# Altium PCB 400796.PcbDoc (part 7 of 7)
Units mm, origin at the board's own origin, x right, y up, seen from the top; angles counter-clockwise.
Board outline 53 x 53 mm, 6 copper layers (Top Layer, Mid Layer 1, Mid Layer 2, Mid Layer 3, Mid Layer 4, Bottom Layer), stack 1.494 mm thick; 319 components, 236 nets, 1249 pads, 2569 vias.
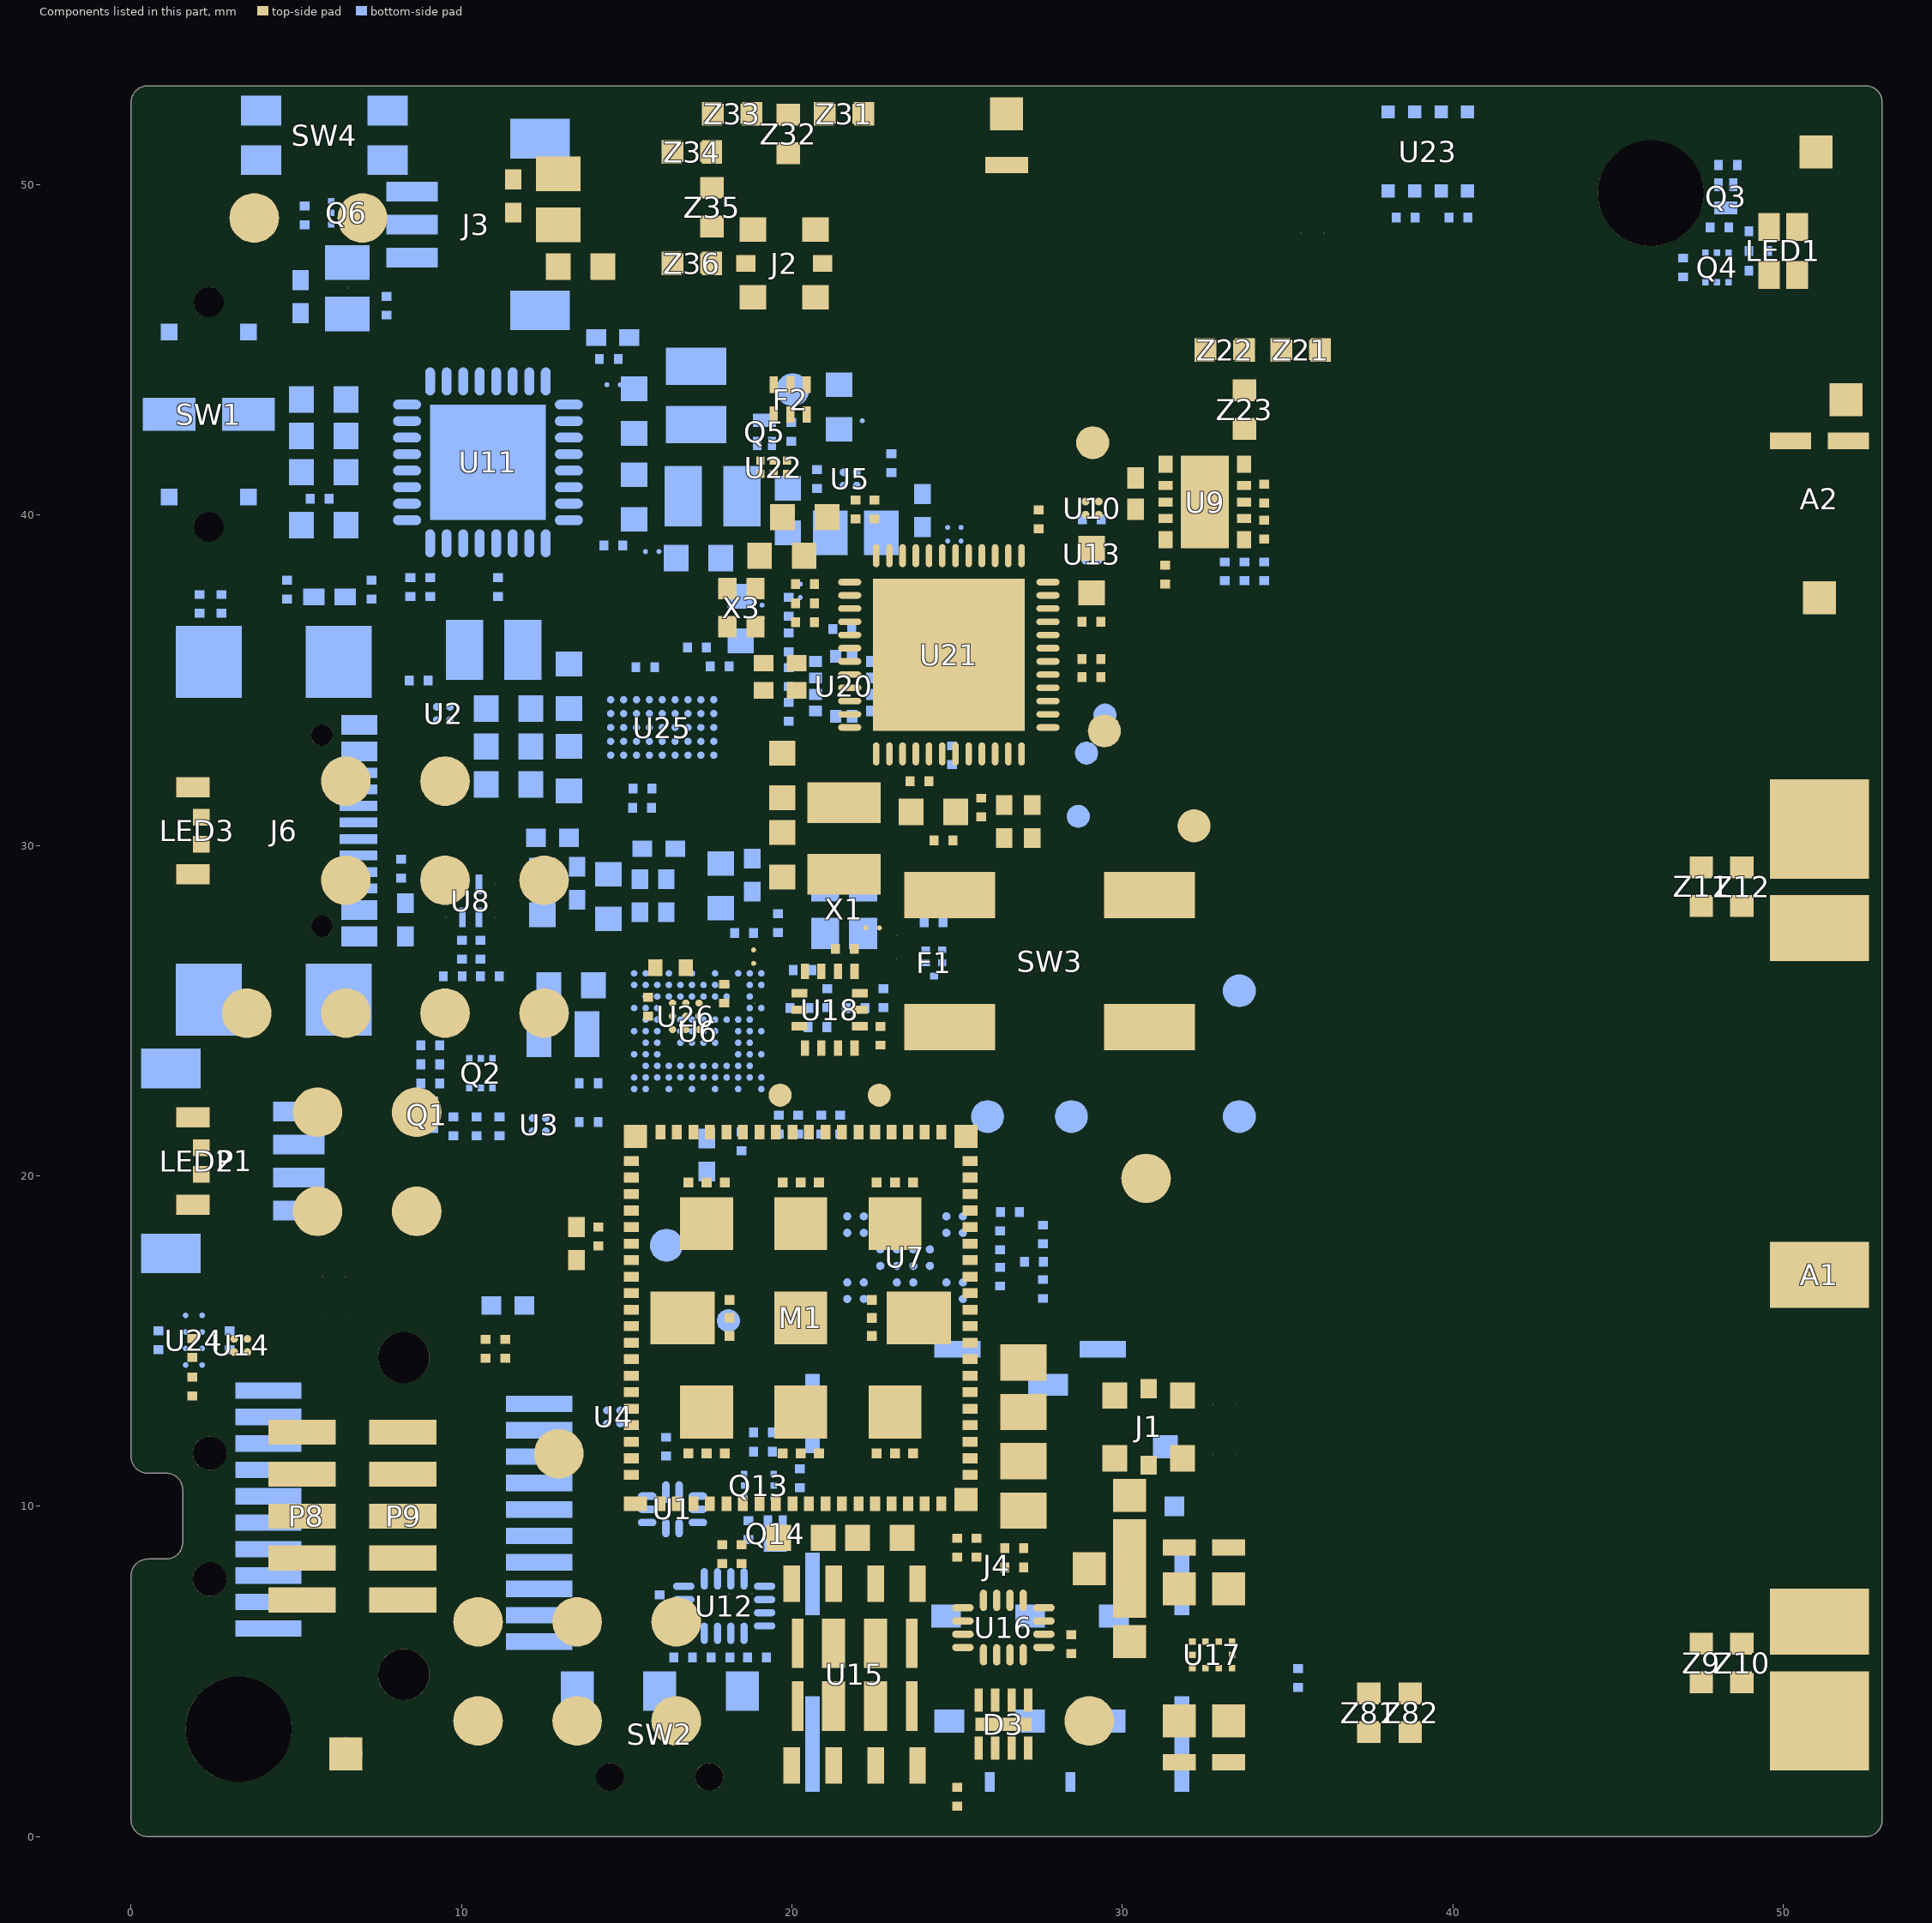
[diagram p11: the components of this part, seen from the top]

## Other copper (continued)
Bottom Layer:
  rectangle net 1V8_SW: 17.495,37.175 19.614,37.925
  region net 3V3_IND: 18.487,38.314 18.487,39.989 17.987,39.989 17.987,38.314
  region net 3V3: 9.275,13.075 9.275,11.4 9.775,11.4 9.775,13.075
  region net VBAT_nRF70: 9.375,33.25 8.4,33.25 8.4,31.45 9.375,31.45
  rectangle net VOUT_BUCK3: 9.525,31.45 10.655,33.4
  region net VBUS: 6.925,37.9 6.925,38.4 5.075,38.4 5.075,37.9
  rectangle net VBUS_CONN: 7.225,32.55 7.75,33.15
  region net GND: 23.794,26.876 23.794,28.176 23.33,28.176 23.33,26.876
  region net VSYS_SW: 10.65,16.725 10.65,15.05 11.15,15.05 11.15,16.725
  rectangle net GND: 22.25,25.836 23.2,26.125
  rectangle net GND: 16.525,23.88 17.775,24.88
  region net SW3: 14.168,33.155 14.245,33.232 cw(c14.3,33.178) 14.3,33.255 14.487,33.255 14.487,33.095 14.263,32.87 14.168,32.965 14.168,33.154
  region net VSYS_SW: 14.33,32.43 cw(c14.48,32.43) 14.374,32.536 14.458,32.62 14.458,32.664 14.479,32.664 14.499,32.644 14.496,32.641 14.496,32.438
  region net SW0: 14.168,33.995 14.245,33.918 ccw(c14.3,33.972) 14.3,33.895 14.487,33.895 14.487,34.055 14.263,34.28 14.168,34.185 14.168,33.996
  region net VSYS_SW: 14.33,34.72 ccw(c14.48,34.72) 14.374,34.614 14.458,34.53 14.458,34.486 14.479,34.486 14.499,34.506 14.496,34.509 14.496,34.712
  region net VBAT_nRF70: 8.4,32.975 8.4,33.175 cw(c8.65,33.175) 8.65,33.425 ccw(c8.65,33.624) 8.791,33.483 9.001,33.694 9.001,32.975 8.7,32.975
  region net VOUT_BUCK3: 10.375,32.975 10.375,33.175 ccw(c10.125,33.175) 10.125,33.425 cw(c10.125,33.624) 9.984,33.483 9.774,33.694 9.774,32.975 10.075,32.975
  region net VOUT_BUCK3: 9.525,33.8 cw(c9.65,33.8) 9.65,33.925 cw(c9.65,33.804) 9.735,33.89 9.75,33.875 cw(c8.905,33.03) 10.1,33.03 10.1,32.8 9.575,32.8 cw(c9.695,32.921) 9.525,32.921 9.525,33.425
  region net VBAT_nRF70: 9.375,33.8 ccw(c9.25,33.8) 9.25,33.925 ccw(c9.25,33.804) 9.165,33.89 9.15,33.875 ccw(c9.995,33.03) 8.8,33.03 8.8,32.8 9.325,32.8 ccw(c9.205,32.921) 9.375,32.921 9.375,33.425
  region net VDD_nRF53: 12.275,21.35 ccw(c12.15,21.35) 12.15,21.475 ccw(c12.15,21.354) 12.065,21.44 12.05,21.425 ccw(c12.895,20.58) 11.7,20.58 11.7,20.175 12.2,20.175 12.2,20.29 cw(c12.285,20.29) 12.225,20.35 ccw(c12.104,20.471) 12.275,20.471 12.275,20.975
  region net 1V8_SW: 12.425,21.35 cw(c12.55,21.35) 12.55,21.475 cw(c12.55,21.354) 12.635,21.44 12.65,21.425 cw(c11.805,20.58) 13,20.58 13,20.175 12.5,20.175 12.5,20.29 ccw(c12.415,20.29) 12.475,20.35 cw(c12.596,20.471) 12.425,20.471 12.425,20.975
  region net VDD_nRF91_RES: 14.4,12.625 cw(c14.4,12.5) 14.525,12.5 cw(c14.404,12.5) 14.49,12.415 14.475,12.4 cw(c13.63,13.245) 13.63,12.05 13.225,12.05 13.225,12.55 13.34,12.55 ccw(c13.34,12.635) 13.4,12.575 cw(c13.521,12.454) 13.521,12.625 14.025,12.625
  region net VDD_nRF91: 14.4,12.775 ccw(c14.4,12.9) 14.525,12.9 ccw(c14.404,12.9) 14.49,12.985 14.475,13 ccw(c13.63,12.155) 13.63,13.35 13.225,13.35 13.225,12.85 13.34,12.85 cw(c13.34,12.765) 13.4,12.825 ccw(c13.521,12.946) 13.521,12.775 14.025,12.775
  region net 1V8_IND: 17.393,46.2 16.593,47 14.5,47 13.525,47 13.525,45.572 14.375,45.572 14.375,45.885 14.69,46.2
  region net VSYS: 3.047,45.05 3.047,46.622 5.099,46.622 7.222,46.622 7.222,45.572 5.067,45.572 4.545,45.05
  region net 3V3: 22.425,39.897 22.425,39.042 24.798,39.042 24.798,39.897 22.468,39.897
  region net VBUS: 7.499,42.178 7.677,42 8.577,42 8.663,41.914 8.663,41.765 8.599,41.7 7.491,41.7 7.313,41.878 5.829,41.878 5.829,42.803 6.874,42.803
  pour cut-out: 20.85,36 20.85,34.25 23.05,34.25 23.05,36 23.075,36
  region net VBUS: 5.85,37.775 5.975,37.9 6.225,37.9 6.225,38.4 4.832,38.4 4.575,38.143 4.575,37.9 5.075,37.9 5.2,37.775 5.2,37.675 5.85,37.675
  pour cut-out: 11.725,32.6 11.125,32.6 11.125,34.55 11.725,34.55
  region net VBUS_CONN: 8.623,28.523 9.7,28.523 9.7,29.255 8.405,29.255 7.5,28.35 7.325,28.35 7.325,27.75 7.85,27.75
  region net VBAT: 8.4,40.7 7.875,40.7 7,39.825 6.475,39.3 6.025,39.3 6.025,40.1 6.6,40.1 6.7,40.2 7.5,41 8.4,41
  pour cut-out: 12.65,43.45 8.95,43.45 8.95,39.75 12.65,39.75
  region net PVSS1: 15.625,45.65 14.875,45.65 14.875,44.949 14.309,44.383 13.8,44.383 13.8,43.225 13.575,43 13.25,43 13.25,42.7 13.775,42.7 14.525,43.45 15.625,43.45
  region net NetC9_2: 14.3,42 14.825,42.525 14.825,42.85 15.625,42.85 15.625,40.85 14.825,40.85 14.825,41.175 14.3,41.7
  region net 1V8_IND: 15.772,46.2 16.175,45.797 16.175,43.925 18.01,43.925 18.01,45.583 16.868,46.725 15.772,46.725
  pour cut-out: 18.264,43.925 18.264,41.485 16.175,41.485 16.175,43.925
  region net 3V3_IND: 19.068,38.889 21.362,38.889 21.569,39.096 21.569,39.938 21.428,40.079 19.149,40.079 19.05,40.178 19.05,41.485 17.9,41.485 17.9,39.65 17.475,39.225 17.475,38.3 18.479,38.3
  region net PVSS2: 13.25,41 13.8,41 14.55,40.25 15.625,40.25 15.625,39.875 16.4,39.1 17.275,39.1 17.275,38.3 15.1,38.3 14.75,38.65 14.75,39.525 13.575,40.7 13.25,40.7
  pour cut-out: 17.3,38.834 17.3,38.045 13.938,38.045 13.938,38.834
  pour cut-out: 3.425,42.05 3.425,41.19
  region net NetC9_2: 7.191,41.703 7.394,41.5 8.605,41.5 8.687,41.418 8.687,41.27 8.617,41.2 7.363,41.2 6.941,40.778 5.829,40.778 5.829,41.703
  pour cut-out: 36.75,48.311 42.25,48.311 42.25,53.229 36.75,53.229
  region net 1V8_SW: 12.5,20.175 12.5,19.6 12.675,19.425 13,19.425 13,20.2 12.5,20.2
  region net VDD_nRF53: 11.7,20.175 11.7,19.6 11.875,19.425 12.2,19.425 12.2,20.2 11.7,20.2
  pour cut-out: 19.85,26.38 19.85,29.505 23.266,29.505 23.266,26.38
  pour cut-out: 17.45,26.18 17.45,24.73 19.225,24.73 19.225,26.18
  pour cut-out: 20.87,26.08 20.87,25.925 21.35,25.925 21.35,25.355 19.175,25.355 19.175,26.08
Multi-Layer:
  pour cut-out: 38.628,45.61 38.628,44.39 33.098,44.39 33.098,45.61
  pour cut-out: 33.098,44.405 33.098,42.009 34.32,42.009 34.32,44.405
  pour cut-out: 16.97,51.555 16.97,47.048 18.191,47.048 18.191,51.555
  pour cut-out: 22.5,52.76 22.5,51.54 16.97,51.54 16.97,52.76
  pour cut-out: 22.5,53 30.5,53 30.5,45 22.5,45
  pour cut-out: 36.6,0.25 36.6,47 54.2,47 54.2,0.25

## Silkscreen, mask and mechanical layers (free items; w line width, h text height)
Top Overlay:
  region: 38.855,52.403 ccw(c38.602,49.887) 38.855,47.37 38.855,48.129 cw(c38.602,49.887) 38.855,51.644
  region: 41.167,50.266 cw(c42.902,49.887) 43.155,51.644 43.155,52.403 ccw(c42.902,49.887) 43.155,47.37 43.155,48.129 cw(c42.902,49.887) 41.167,49.507 42.902,49.507 42.902,50.266
  text "'.PCBNumber'" at 43.89,51.58 h1.78
  text "BUTTON 2" at 1.35,50.95 h1.8
  text "LED1" at 51.099,49.979 h1.8 r270
  text "ON" at 0.136,47.55 h1.8 r270
  text "POWER" at 2.85,47.55 h1.8 r270
  text ".PCBRevision" at 43.889,47.214 h1.02
  text "OFF" at 0.136,42.05 h1.8 r270
  text "For evaluation only; / not FCC approved for resale." at 4.054,40.687 h1.4
  text "Thingy:91 X" at 6.875,37.896 h1.78
  text "CHARGE LED" at 2.609,33.858 h1.8 r270
  text "LED2" at 2.681,22.168 h1.8 r270
  text "BUTTON 1" at 23.3,21.866 h1.8
  text "SWD" at 14.5,1.375 h1.4
  text "nRF53" at 12.35,0.15 h1.4
  text "nRF91" at 15.95,0.15 h1.4
Board Outline:
  lines w0.15: 52.5,0 ccw(c52.5,0.5) 53,0.5 ; 52.5,0 ccw(c52.5,0.5) 53,0.5 ; 52.5,0 0.5,0 cw(c0.5,0.5) 0,0.5 0,7.9 cw(c0.5,7.9) 0.5,8.4 1.06,8.4 ccw(c1.06,8.9) 1.56,8.9 1.56,10.5 ccw(c1.06,10.5) 1.06,11 0.5,11 cw(c0.5,11.5) 0,11.5 0,52.5 cw(c0.5,52.5) 0.5,53 52.5,53 cw(c52.5,52.5) 53,52.5 53,0.5
Board Other:
  drawing of 2516 lines, arcs and shapes, not listed
Dimension:
  drawing of 463 lines, arcs and shapes, not listed
Top Impedance Info:
  lines w0.29: 18.075,30.9 17.502,30.9 cw(c17.502,32.048) 16.354,32.048 16.354,40.077 cw(c17.526,40.077) 17.526,41.25 19.05,41.25 ; 19.45,41.682 19.45,43.15 ; 19.875,41.25 22.85,41.25 cw(c22.85,40.35) 23.75,40.35 23.75,38.775 ; 19.95,43.95 19.95,44.376 cw(c21.024,44.376) 20.265,45.136 20.275,45.146 cw(c20.8,44.622) 20.8,45.364 ccw(c20.8,45.959) 21.22,45.538 21.254,45.572 ccw(c20.421,46.406) 21.6,46.406 21.6,47.201 ccw(c21.173,47.201) 21.475,47.503 ccw(c21.183,47.211) 21.183,47.623 20.928,47.623 ; 20.475,43.05 23.324,43.05 cw(c23.324,41.824) 24.55,41.824 24.55,38.775
  lines w0.638: 24.513,22.086 24.513,22 cw(c25.436,22) 24.783,22.652 cw(c25.367,22.068) 25.367,22.894 32.036,22.894 ccw(c32.036,25.169) 33.645,23.56 ccw(c32.075,25.131) 34.296,25.131 34.296,31.648 ccw(c31.756,31.648) 33.552,33.444 32.039,34.956 cw(c33.836,36.752) 31.296,36.752 31.296,37.78 ; 26.06,17.946 27.386,17.946 cw(c27.386,15.406) 29.182,17.202 30.056,16.328 cw(c28.26,14.532) 30.8,14.532 30.8,13.557 ; 30.564,10.64 ccw(c29.994,11.21) 30.8,11.21 ; 31.312,38.625 31.312,39.256 ; 33.687,41.543 33.687,42.577 33.7,42.59 ; 33.7,43.81 33.7,44.99 33.71,45 34.79,45
  text "50 ohm impedance, CPW" at 11.45,29.05 h1.78
  text "50 ohm impedance, CPW" at 21.359,19.523 h1.78
Bottom Impedance Info:
  lines w0.083: 5.9,30.05 cw(c6.262,29.688) 6.262,30.2 6.88,30.2 cw(c7.23,29.85) 7.23,30.345 7.738,30.345 ccw(c7.738,31.008) 8.206,30.539 cw(c8.776,29.969) 8.776,30.775 9.708,30.775 cw(c9.708,30.291) 10.05,30.633 cw(c9.83,30.412) 10.142,30.412 10.142,29.342 cw(c9.047,29.342) 9.821,28.568 9.537,28.283 cw(c9.275,28.545) 9.275,28.175 cw(c9.275,27.793) 9.545,28.063 10.093,27.516 cw(c9.911,27.334) 10.168,27.334 cw(c10.09,27.334) 10.145,27.279 10.02,27.153 ; 5.9,30.85 ccw(c6.262,31.212) 6.262,30.7 6.88,30.7 ccw(c7.23,31.05) 7.23,30.555 7.738,30.555 ccw(c7.738,31.008) 8.058,30.688 cw(c8.776,29.969) 8.776,30.985 9.708,30.985 cw(c9.708,30.291) 10.199,30.782 cw(c9.83,30.412) 10.352,30.412 10.352,29.342 ccw(c11.225,29.342) 10.608,28.725 11.039,28.293 ccw(c11.325,28.579) 11.325,28.175 ccw(c11.325,27.79) 11.053,28.062 10.52,27.529 ; 10.572,27.153 10.447,27.278 cw(c10.485,27.316) 10.431,27.316 cw(c10.734,27.316) 10.52,27.529 ; 15.225,26.13 15.129,26.226 ccw(c14.686,25.783) 14.686,26.409 12.334,26.409 ccw(c12.334,25.994) 12.041,26.288 ; 15.575,26.13 15.368,26.337 ccw(c14.686,25.655) 14.686,26.619 12.334,26.619 ccw(c12.334,25.994) 11.892,26.436 11.825,26.369 ccw(c12.183,26.011) 11.677,26.011 11.677,25.697 cw(c11.58,25.697) 11.648,25.628 cw(c10.92,26.357) 11.105,25.343 cw(c10.92,26.357) 10.92,25.327 10.714,25.327 cw(c10.714,25.539) 10.564,25.389 10.512,25.441 cw(c10.781,25.71) 10.401,25.71 cw(c10.858,25.71) 10.535,26.033 10.572,26.07 10.572,26.583 ; 10.02,26.583 10.02,26.583 ; 10.02,26.583 10.02,26.07 10.057,26.033 cw(c9.734,25.71) 10.191,25.71 ccw(c10.781,25.71) 10.364,25.292 10.415,25.24 ccw(c10.714,25.539) 10.714,25.116 10.96,25.116 ccw(c10.96,26.261) 11.128,25.129 ccw(c10.96,26.261) 11.769,25.452 11.797,25.48 ccw(c11.58,25.697) 11.887,25.697 11.887,26.011 cw(c12.183,26.011) 11.974,26.22 ; 10.52,27.529 ccw(c10.734,27.316) 10.52,27.529 ; 10.52,27.529 10.52,27.529 ; 10.572,26.583 10.572,26.583 ; 11.974,26.22 ccw(c12.183,26.011) 11.974,26.22 ; 11.974,26.22 11.974,26.22 ; 11.974,26.22 12.041,26.288 ; 12.041,26.288 ccw(c12.334,25.994) 12.041,26.288 ; 12.041,26.288 12.041,26.288
  lines w0.29: 18.075,30.9 23.65,30.9 cw(c23.65,30) 24.55,30 24.55,26.851 ; 22.231,25.08 23.704,25.08 ccw(c23.704,25.676) 24.299,25.676 24.299,26.051
  text "50 ohm impedance, CPW" at 18.875,31.45 h1.78
  text "90 ohm differential impedance" at 1.541,23.705 h1.78
Mechanical 31:
  lines w0.15: -36.156,16.746 -1,16.746 ; -36.156,24.154 -1,24.154 ; -36.156,25.424 -1,25.424 ; -36.156,27.576 -1,27.576 ; -36.014,3.869 -1,3.869 ; -36.014,15.476 -1,15.476
Mechanical 32:
  lines w0.15: -40.007,3.95 -1.5,3.95 -1.5,15.45 -40.007,15.45 ; -38.402,21.843 -1.5,21.843 -1.5,31.156 -38.402,31.156 ; -33.928,38.725 -2,38.725 ; -33.91,37.244 -2,37.244 ; -33.892,49.238 -2,49.238 ; -33.892,50.226 -2,50.226 ; -31.899,39.748 -2,39.748 -2,48.25 -31.899,48.25

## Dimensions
20.975,57.95 to 4.225,57.95 on Dimension
4.225,57.95 to 4.225,71.95 on Dimension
